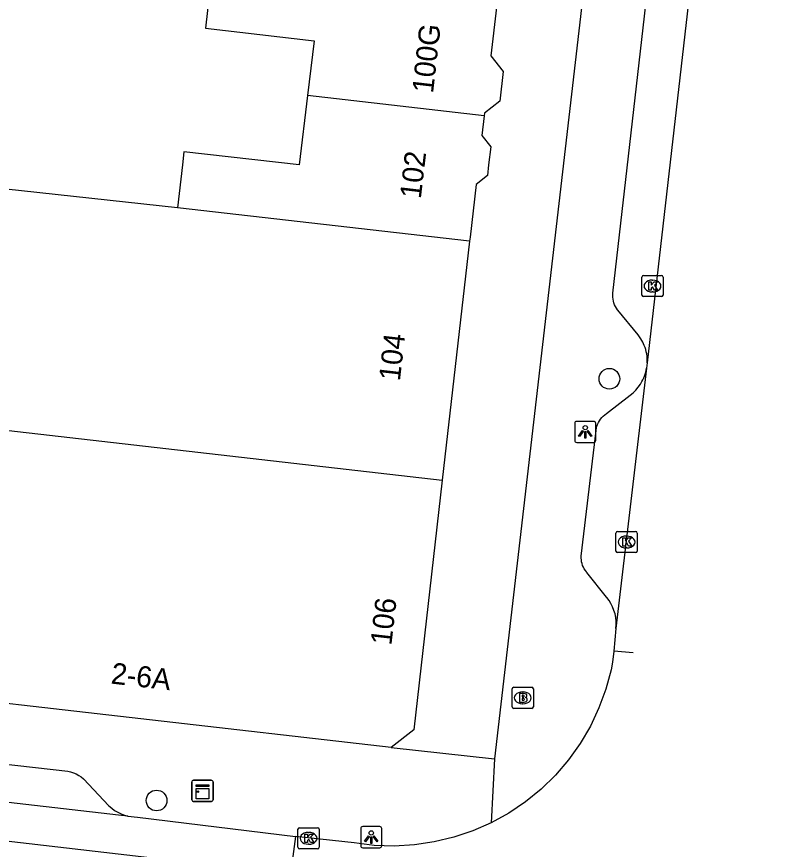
# Model space of a CAD drawing. Extents: x 161696 to 162377, y 380761 to 381673.
# Drawn here: x 162273.45 to 162309.12, y 381217.63 to 381257.01 of the extents above; entities that cross this region are included whole.
import ezdxf

# ---------------------------------------------------------------- set-up
doc = ezdxf.new("R2010")
doc.units = 0
for name, color, linetype in [('IMGEO_Boom', 7, 'Continuous'), ('IMGEO_Brandkraan', 7, 'Continuous'), ('IMGEO_Kast', 7, 'Continuous'), ('IMGEO_Kolk', 7, 'Continuous'), ('IMGEO_Lichtpunt', 7, 'Continuous'), ('IMGEO_Pand', 7, 'Continuous'), ('IMGEO_Pand_nummerreeks', 7, 'Continuous'), ('IMGEO_Rijbaan_lokaal_gesloten', 7, 'Continuous'), ('IMGEO_Voetpad_open', 7, 'Continuous')]:
    doc.layers.add(name, color=color, linetype=linetype)

msp = doc.modelspace()

# ---------------------------------------------------------------- linework, layer by layer
at = {"layer": 'IMGEO_Boom'}
for centre in [(162301.469, 381239.887), (162280.063, 381219.942)]:
    msp.add_circle(centre, 0.489, dxfattribs=at)
at = {"layer": 'IMGEO_Brandkraan'}
for p, q in [((162296.947, 381225.299), (162297.799, 381225.299)), ((162296.872, 381224.373), (162296.872, 381225.225)), ((162297.36, 381225.079), (162297.385, 381225.079)), ((162297.873, 381225.225), (162297.873, 381224.373)), ((162297.383, 381224.519), (162297.358, 381224.519)), ((162297.799, 381224.299), (162296.947, 381224.299))]:
    msp.add_line(p, q, dxfattribs=at)
for points in [[(162296.947, 381225.299), (162297.799, 381225.299)], [(162296.872, 381224.373), (162296.872, 381225.225)], [(162297.22, 381224.999), (162297.22, 381224.599), (162297.433, 381224.599)], [(162297.451, 381224.999), (162297.22, 381224.999)], [(162297.399, 381224.918), (162297.345, 381224.918), (162297.345, 381224.842)], [(162297.873, 381225.225), (162297.873, 381224.373)], [(162297.345, 381224.842), (162297.398, 381224.842)], [(162297.407, 381224.766), (162297.345, 381224.766), (162297.345, 381224.685)], [(162297.345, 381224.685), (162297.407, 381224.685)], [(162297.799, 381224.299), (162296.947, 381224.299)]]:
    msp.add_lwpolyline(points, dxfattribs=at)
for centre, radius, start, end in [((162296.949, 381225.223), 0.0765, 91.552, 178.448), ((162296.949, 381225.223), 0.0765, 91.552, 178.448), ((162297.797, 381225.223), 0.0765, 1.552, 88.448), ((162297.797, 381225.223), 0.0765, 1.552, 88.448), ((162297.4, 381224.88), 0.0379, 267.8285, 90.9355), ((162297.455, 381224.854), 0.145, 59.4692, 91.5367), ((162297.48, 381224.901), 0.0922, 285.5137, 58.1501), ((162297.408, 381224.725), 0.0404, 269.8759, 90.5077), ((162297.439, 381224.85), 0.251, 268.6676, 293.5347), ((162297.485, 381224.709), 0.105, 301.3115, 78.989), ((162296.949, 381224.375), 0.0765, 181.552, 268.448), ((162296.949, 381224.375), 0.0765, 181.552, 268.448), ((162297.797, 381224.375), 0.0765, 271.552, 358.448), ((162297.797, 381224.375), 0.0765, 271.552, 358.448)]:
    msp.add_arc(centre, radius, start, end, dxfattribs=at)
for centre, major_axis, ratio, start_param, end_param in [((162297.359, 381224.799), (-0.387, 0.002), 0.722429, 4.712389, 7.853982), ((162297.384, 381224.799), (-0.39, 0.002), 0.717154, 1.570796, 4.712389)]:
    msp.add_ellipse(centre, major_axis=major_axis, ratio=ratio, start_param=start_param, end_param=end_param, dxfattribs=at)
at = {"layer": 'IMGEO_Kast'}
for p, q in [((162281.733, 381219.972), (162281.733, 381220.813)), ((162281.733, 381220.813), (162281.733, 381219.972)), ((162281.808, 381220.897), (162282.649, 381220.897)), ((162282.649, 381220.897), (162281.808, 381220.897)), ((162282.733, 381220.822), (162282.733, 381219.981)), ((162282.733, 381219.981), (162282.733, 381220.822)), ((162282.658, 381219.897), (162281.817, 381219.897)), ((162281.817, 381219.897), (162282.658, 381219.897))]:
    msp.add_line(p, q, dxfattribs=at)
for points in [[(162281.928, 381220.687), (162282.528, 381220.687), (162282.528, 381220.602), (162281.928, 381220.602), (162281.928, 381220.687)], [(162281.928, 381220.512), (162282.528, 381220.512), (162282.528, 381220.023), (162281.928, 381220.023), (162281.928, 381220.512)]]:
    msp.add_lwpolyline(points, dxfattribs=at)
msp.add_circle((162282.012, 381220.361), 0.0377, dxfattribs=at)
for centre, start, end in [((162281.811, 381220.819), 92.4484, 184.2845), ((162281.811, 381220.819), 92.4484, 184.2845), ((162282.655, 381220.819), 2.4484, 94.2845), ((162282.655, 381220.819), 2.4484, 94.2845), ((162281.811, 381219.975), 182.4484, 274.2845), ((162281.811, 381219.975), 182.4484, 274.2845), ((162282.655, 381219.975), 272.4484, 4.2845), ((162282.655, 381219.975), 272.4484, 4.2845)]:
    msp.add_arc(centre, 0.0779, start, end, dxfattribs=at)
at = {"layer": 'IMGEO_Kolk'}
for p, q in [((162303.004, 381243.847), (162303.004, 381244.699)), ((162303.079, 381244.773), (162303.931, 381244.773)), ((162303.492, 381244.553), (162303.517, 381244.553)), ((162304.005, 381244.699), (162304.005, 381243.847)), ((162303.931, 381243.773), (162303.079, 381243.773)), ((162303.515, 381243.993), (162303.49, 381243.993)), ((162301.779, 381231.74), (162301.779, 381232.592)), ((162301.854, 381232.666), (162302.706, 381232.666)), ((162302.267, 381232.446), (162302.292, 381232.446)), ((162302.78, 381232.592), (162302.78, 381231.74)), ((162302.706, 381231.666), (162301.854, 381231.666)), ((162302.29, 381231.886), (162302.265, 381231.886)), ((162286.747, 381217.729), (162286.747, 381218.581)), ((162286.822, 381218.655), (162287.674, 381218.655)), ((162287.748, 381218.581), (162287.748, 381217.729)), ((162287.235, 381218.435), (162287.26, 381218.435)), ((162287.258, 381217.875), (162287.233, 381217.875)), ((162287.674, 381217.655), (162286.822, 381217.655))]:
    msp.add_line(p, q, dxfattribs=at)
for points in [[(162303.004, 381243.847), (162303.004, 381244.699)], [(162303.079, 381244.773), (162303.931, 381244.773)], [(162304.005, 381244.699), (162304.005, 381243.847)], [(162303.325, 381244.473), (162303.448, 381244.473), (162303.448, 381244.322), (162303.578, 381244.473), (162303.742, 381244.473), (162303.596, 381244.322), (162303.749, 381244.073), (162303.597, 381244.073), (162303.512, 381244.237), (162303.448, 381244.17), (162303.448, 381244.073), (162303.325, 381244.073), (162303.325, 381244.473)], [(162303.931, 381243.773), (162303.079, 381243.773)], [(162301.779, 381231.74), (162301.779, 381232.592)], [(162301.854, 381232.666), (162302.706, 381232.666)], [(162302.1, 381232.366), (162302.223, 381232.366), (162302.223, 381232.215), (162302.353, 381232.366), (162302.517, 381232.366), (162302.371, 381232.215), (162302.524, 381231.966), (162302.372, 381231.966), (162302.287, 381232.13), (162302.223, 381232.063), (162302.223, 381231.966), (162302.1, 381231.966), (162302.1, 381232.366)], [(162302.78, 381232.592), (162302.78, 381231.74)], [(162302.706, 381231.666), (162301.854, 381231.666)], [(162286.747, 381217.729), (162286.747, 381218.581)], [(162286.822, 381218.655), (162287.674, 381218.655)], [(162287.748, 381218.581), (162287.748, 381217.729)], [(162287.068, 381218.355), (162287.191, 381218.355), (162287.191, 381218.204), (162287.321, 381218.355), (162287.485, 381218.355), (162287.339, 381218.204), (162287.492, 381217.955), (162287.34, 381217.955), (162287.255, 381218.119), (162287.191, 381218.052), (162287.191, 381217.955), (162287.068, 381217.955), (162287.068, 381218.355)], [(162287.674, 381217.655), (162286.822, 381217.655)]]:
    msp.add_lwpolyline(points, dxfattribs=at)
for centre, start, end in [((162303.081, 381244.697), 91.552, 178.448), ((162303.081, 381244.697), 91.552, 178.448), ((162303.929, 381244.697), 1.552, 88.448), ((162303.929, 381244.697), 1.552, 88.448), ((162303.081, 381243.849), 181.552, 268.448), ((162303.081, 381243.849), 181.552, 268.448), ((162303.929, 381243.849), 271.552, 358.448), ((162303.929, 381243.849), 271.552, 358.448), ((162301.856, 381232.59), 91.552, 178.448), ((162301.856, 381232.59), 91.552, 178.448), ((162302.704, 381232.59), 1.552, 88.448), ((162302.704, 381232.59), 1.552, 88.448), ((162301.856, 381231.742), 181.552, 268.448), ((162301.856, 381231.742), 181.552, 268.448), ((162302.704, 381231.742), 271.552, 358.448), ((162302.704, 381231.742), 271.552, 358.448), ((162286.824, 381218.579), 91.552, 178.448), ((162286.824, 381218.579), 91.552, 178.448), ((162287.672, 381218.579), 1.552, 88.448), ((162287.672, 381218.579), 1.552, 88.448), ((162286.824, 381217.731), 181.552, 268.448), ((162286.824, 381217.731), 181.552, 268.448), ((162287.672, 381217.731), 271.552, 358.448), ((162287.672, 381217.731), 271.552, 358.448)]:
    msp.add_arc(centre, 0.0765, start, end, dxfattribs=at)
for centre, major_axis, ratio, start_param, end_param in [((162303.491, 381244.273), (-0.387, 0.002), 0.722429, 4.712389, 7.853982), ((162303.516, 381244.273), (-0.39, 0.002), 0.717154, 1.570796, 4.712389), ((162302.266, 381232.166), (-0.387, 0.002), 0.722429, 4.712389, 7.853982), ((162302.291, 381232.166), (-0.39, 0.002), 0.717154, 1.570796, 4.712389), ((162287.234, 381218.155), (-0.387, 0.002), 0.722429, 4.712389, 7.853982), ((162287.259, 381218.155), (-0.39, 0.002), 0.717154, 1.570796, 4.712389)]:
    msp.add_ellipse(centre, major_axis=major_axis, ratio=ratio, start_param=start_param, end_param=end_param, dxfattribs=at)
at = {"layer": 'IMGEO_Lichtpunt'}
for p, q in [((162300.73, 381237.873), (162299.922, 381237.873)), ((162300.73, 381237.873), (162299.922, 381237.873)), ((162299.828, 381237.778), (162299.828, 381236.971)), ((162299.828, 381237.778), (162299.828, 381236.971)), ((162300.824, 381236.971), (162300.824, 381237.778)), ((162300.824, 381236.971), (162300.824, 381237.778)), ((162299.922, 381236.877), (162300.73, 381236.877)), ((162299.922, 381236.877), (162300.73, 381236.877)), ((162289.713, 381218.611), (162289.713, 381217.804)), ((162289.713, 381218.611), (162289.713, 381217.804)), ((162290.615, 381218.706), (162289.807, 381218.706)), ((162290.615, 381218.706), (162289.807, 381218.706)), ((162290.709, 381217.804), (162290.709, 381218.611)), ((162290.709, 381217.804), (162290.709, 381218.611)), ((162289.807, 381217.71), (162290.615, 381217.71)), ((162289.807, 381217.71), (162290.615, 381217.71))]:
    msp.add_line(p, q, dxfattribs=at)
for points in [[(162300.202, 381237.442), (162300.241, 381237.414), (162300.053, 381237.152), (162300.015, 381237.179), (162300.202, 381237.442)], [(162300.304, 381237.394), (162300.351, 381237.394), (162300.351, 381237.072), (162300.304, 381237.072), (162300.304, 381237.394)], [(162300.414, 381237.414), (162300.452, 381237.441), (162300.639, 381237.179), (162300.6, 381237.151), (162300.414, 381237.414)], [(162290.087, 381218.275), (162290.126, 381218.247), (162289.938, 381217.985), (162289.9, 381218.012), (162290.087, 381218.275)], [(162290.189, 381218.227), (162290.236, 381218.227), (162290.236, 381217.905), (162290.189, 381217.905), (162290.189, 381218.227)], [(162290.299, 381218.247), (162290.337, 381218.274), (162290.524, 381218.012), (162290.485, 381217.984), (162290.299, 381218.247)]]:
    msp.add_lwpolyline(points, dxfattribs=at)
for centre in [(162300.327, 381237.576), (162290.212, 381218.409)]:
    msp.add_circle(centre, 0.0994, dxfattribs=at)
for centre, start, end in [((162299.922, 381237.778), 90, 180), ((162299.922, 381237.778), 90, 180), ((162300.73, 381237.778), 0, 90), ((162300.73, 381237.778), 0, 90), ((162299.922, 381236.971), 180, 270), ((162299.922, 381236.971), 180, 270), ((162300.73, 381236.971), 270, 0), ((162300.73, 381236.971), 270, 360), ((162289.807, 381218.611), 90, 180), ((162289.807, 381218.611), 90, 180), ((162290.615, 381218.611), 0, 90), ((162290.615, 381218.611), 0, 90), ((162289.807, 381217.804), 180, 270), ((162289.807, 381217.804), 180, 270), ((162290.615, 381217.804), 270, 0), ((162290.615, 381217.804), 270, 360)]:
    msp.add_arc(centre, 0.0946, start, end, dxfattribs=at)
at = {"layer": 'IMGEO_Pand'}
for points in [[(162282.659, 381258.995), (162282.37, 381256.465), (162287.509, 381255.877), (162287.196, 381253.284)], [(162296.13, 381257.444), (162295.864, 381255.154), (162296.445, 381254.42), (162296.282, 381253.018), (162295.564, 381252.449), (162295.55, 381252.324)], [(162287.196, 381253.284), (162286.8, 381250), (162281.359, 381250.617), (162281.289, 381250), (162281.057, 381247.971)], [(162295.55, 381252.324), (162287.196, 381253.284)], [(162295.55, 381252.324), (162295.441, 381251.388), (162295.858, 381250.861), (162295.758, 381250), (162295.701, 381249.507), (162295.167, 381249.083), (162294.882, 381246.59), (162294.86, 381246.396)], [(162281.057, 381247.971), (162266.291, 381249.587), (162265.551, 381243.111), (162264.983, 381238.143), (162268.913, 381237.694)], [(162294.86, 381246.396), (162281.057, 381247.971)], [(162294.86, 381246.396), (162293.569, 381235.098)], [(162268.913, 381237.694), (162268.938, 381237.91), (162293.569, 381235.098)], [(162293.569, 381235.098), (162292.219, 381223.29), (162291.159, 381222.448)], [(162291.159, 381222.448), (162267.479, 381225.155), (162267.502, 381225.358)]]:
    msp.add_lwpolyline(points, dxfattribs=at)
at = {"layer": 'IMGEO_Rijbaan_lokaal_gesloten'}
for points in [[(162309.123, 381292.03), (162307.201, 381275.19), (162303.256, 381240.642)], [(162303.256, 381240.642), (162303.227, 381240.389)], [(162303.227, 381240.389), (162301.777, 381228.077)], [(162301.777, 381228.077), (162301.672, 381227.011)], [(162301.672, 381227.011), (162301.618, 381226.491), (162301.545, 381226.128), (162301.3, 381225.21), (162300.973, 381224.318), (162300.568, 381223.459), (162300.088, 381222.639), (162299.537, 381221.866), (162298.919, 381221.145), (162298.239, 381220.481), (162297.502, 381219.882), (162296.715, 381219.35), (162295.883, 381218.891)], [(162302.598, 381226.919), (162301.672, 381227.011)], [(162286.396, 381216.457), (162220.264, 381224.141), (162220.506, 381225.942)], [(162278.711, 381219.208), (162278.27, 381219.254), (162266.894, 381220.55)], [(162278.711, 381219.208), (162279.168, 381219.16), (162286.631, 381218.235)], [(162295.883, 381218.891), (162295.014, 381218.508), (162294.114, 381218.204), (162293.191, 381217.982), (162292.251, 381217.843), (162291.302, 381217.789), (162290.353, 381217.82), (162289.41, 381217.935), (162286.631, 381218.235)], [(162286.631, 381218.235), (162286.396, 381216.457)]]:
    msp.add_lwpolyline(points, dxfattribs=at)
at = {"layer": 'IMGEO_Voetpad_open'}
for points in [[(162303.119, 381241.466), (162303.046, 381241.625), (162302.96, 381241.778), (162302.861, 381241.922), (162302.822, 381241.972), (162301.865, 381243.139), (162301.858, 381243.148), (162301.803, 381243.223), (162301.755, 381243.303), (162301.714, 381243.387), (162301.681, 381243.474), (162301.656, 381243.564), (162301.639, 381243.656), (162301.63, 381243.749), (162301.63, 381243.842), (162301.637, 381243.935), (162306.786, 381289.038)], [(162302.596, 381278.545), (162296.033, 381221.909)], [(162301.777, 381228.077), (162301.789, 381228.251), (162301.787, 381228.425), (162301.768, 381228.598), (162301.734, 381228.769), (162301.685, 381228.936), (162301.622, 381229.098), (162301.544, 381229.254), (162301.452, 381229.402), (162301.348, 381229.542), (162301.331, 381229.562), (162300.409, 381230.731), (162300.388, 381230.755), (162300.331, 381230.824), (162300.282, 381230.898), (162300.239, 381230.977), (162300.203, 381231.059), (162300.175, 381231.144), (162300.154, 381231.231), (162300.142, 381231.319), (162300.137, 381231.409), (162300.14, 381231.498), (162300.846, 381237.439), (162300.847, 381237.452), (162300.86, 381237.546), (162300.882, 381237.639), (162300.912, 381237.73), (162300.95, 381237.818), (162300.996, 381237.902), (162301.049, 381237.981), (162301.109, 381238.056), (162301.175, 381238.125), (162301.247, 381238.188), (162301.325, 381238.244), (162302.453, 381239.115), (162302.59, 381239.227), (162302.717, 381239.35), (162302.832, 381239.485), (162302.935, 381239.629), (162302.959, 381239.667)], [(162291.159, 381222.448), (162296.033, 381221.909)], [(162270.288, 381221.968), (162275.867, 381221.329), (162275.995, 381221.299), (162276.13, 381221.255), (162276.261, 381221.199), (162276.386, 381221.132), (162276.504, 381221.054), (162276.615, 381220.965), (162277.81, 381219.685), (162277.942, 381219.572), (162278.083, 381219.472), (162278.233, 381219.384), (162278.389, 381219.31), (162278.552, 381219.251), (162278.711, 381219.208)], [(162296.033, 381221.909), (162295.883, 381218.891)]]:
    msp.add_lwpolyline(points, dxfattribs=at)
for centre, radius, start, end in [((162301.3, 381240.74), 1.959, 357.1283, 21.7513), ((162301.249, 381240.713), 2.004, 328.5593, 350.7117)]:
    msp.add_arc(centre, radius, start, end, dxfattribs=at)

# ---------------------------------------------------------------- texts
at = {"layer": 'IMGEO_Pand_nummerreeks'}
for s, rotation, p in [('100G', 83.537, (162293.132, 381253.365)), ('102', 83.3608, (162292.553, 381248.372)), ('104', 83.48, (162291.564, 381239.754)), ('106', 83.48, (162291.162, 381227.256)), ('2-6A', 353.4797, (162277.877, 381225.476))]:
    msp.add_text(s, height=1, rotation=rotation, dxfattribs=at).set_placement(p)

doc.saveas('drawing.dxf')
